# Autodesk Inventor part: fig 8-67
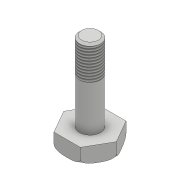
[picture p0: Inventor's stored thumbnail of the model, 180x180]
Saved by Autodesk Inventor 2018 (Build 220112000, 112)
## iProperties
Created: 2016-04
Part Number: fig 8-67
Material: Generic
Document SubType Name: Modeling
Designer: Sandeep
Density: 1 g/cm^3
Appearance: Default
Author: Sandeep
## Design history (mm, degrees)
sketch "Sketch1"
  geometry: C1 r 25 at (0, 0); 1 further point
  constraints: 1 centre point, 1 coincident
  dimensions: "d0" = 50 diameter of C1
extrude "Extrusion1" new body sketch "Sketch1" distance "d1" = 15; taper "d2" = 0 deg
fillet "Fillet1" dims "d3" = 5
sketch "Sketch2"
  geometry: L1 (12.5, 21.651)-(25, 0); L2 (25, 0)-(12.5, -21.651); L3 (12.5, -21.651)-(-12.5, -21.651); L4 (-12.5, -21.651)-(-25, 0); L5 (-25, 0)-(-12.5, 21.651); L6 (-12.5, 21.651)-(12.5, 21.651); 3 further points
  constraints: 12 end point, 1 coincident, 1 horizontal, 15 other
extrude "Extrusion2" cut sketch "Sketch2" distance "d4" = 32.5; taper "d5" = 0 deg
sketch "Sketch3"
  geometry: C1 r 10 at (0, 0); 1 further point
  constraints: 1 centre point, 1 coincident
  dimensions: "d6" = 20 diameter of C1
extrude "Extrusion3" join sketch "Sketch3" distance "d7" = 75; taper "d8" = 0 deg
chamfer "Chamfer1" distance "d9" = 2; stored, may be unused: second distance "d10" = 2, angle "d11" = 45 deg
thread "Thread1" dims "d12" = 30, "d13" = 0
body "Solid1"
